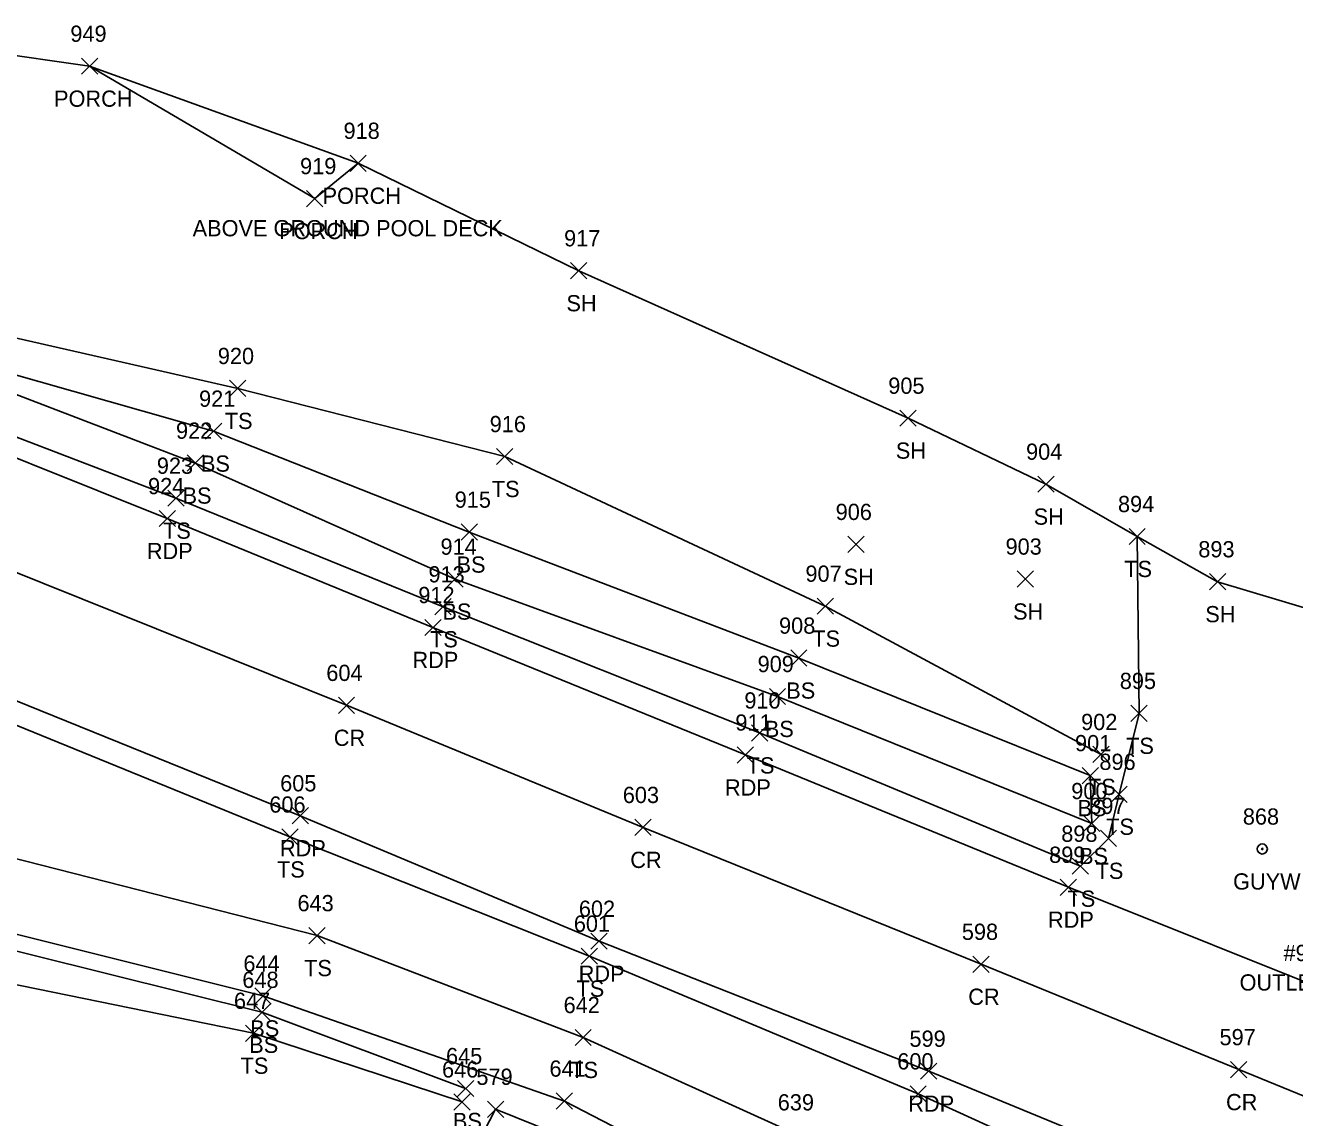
# Model space of a CAD drawing. Extents: x 1599569 to 1610055, y 642560 to 647860.
# Drawn here: x 1602887.6 to 1603043.9, y 647361.4 to 647495.9 of the extents above; entities that cross this region are included whole.
import ezdxf

# ---------------------------------------------------------------- set-up
doc = ezdxf.new("R2010")
doc.units = 0
for name, color, linetype in [('D_C', 7, 'Continuous'), ('L_A', 7, 'Continuous'), ('L_C', 7, 'Continuous'), ('L_I', 7, 'Continuous'), ('L_TIC', 7, 'Continuous'), ('LBF', 7, 'Continuous'), ('LELB', 7, 'Continuous'), ('LSOGP', 7, 'Continuous'), ('P_A', 7, 'Continuous'), ('P_I', 7, 'Continuous'), ('P_TIC', 7, 'Continuous'), ('PET', 7, 'Continuous'), ('PRC', 7, 'Continuous'), ('R_I', 7, 'Continuous'), ('R_TIC', 7, 'Continuous'), ('RDP', 7, 'Continuous'), ('U_A', 7, 'Continuous'), ('U_C', 7, 'Continuous'), ('U_I', 7, 'Continuous'), ('UPGW', 7, 'Continuous')]:
    doc.layers.add(name, color=color, linetype=linetype)

msp = doc.modelspace()

# ---------------------------------------------------------------- linework, layer by layer
at = {"layer": 'L_TIC'}
for points in [[(1602894.48, 647489.89), (1602896.48, 647491.89)], [(1602896.48, 647489.89), (1602894.48, 647491.89)], [(1602927.55, 647477.93), (1602929.55, 647479.93)], [(1602929.55, 647477.93), (1602927.55, 647479.93)], [(1602922.2, 647473.58), (1602924.2, 647475.58)], [(1602924.2, 647473.58), (1602922.2, 647475.58)], [(1602954.71, 647464.69), (1602956.71, 647466.69)], [(1602956.71, 647464.69), (1602954.71, 647466.69)], [(1602912.72, 647450.19), (1602914.72, 647452.19)], [(1602914.72, 647450.19), (1602912.72, 647452.19)], [(1602995.27, 647446.53), (1602997.27, 647448.53)], [(1602997.27, 647446.53), (1602995.27, 647448.53)], [(1602909.75, 647444.93), (1602911.75, 647446.93)], [(1602911.75, 647444.93), (1602909.75, 647446.93)], [(1602907.49, 647440.99), (1602909.49, 647442.99)], [(1602909.49, 647440.99), (1602907.49, 647442.99)], [(1602945.6, 647441.8), (1602947.6, 647443.8)], [(1602947.6, 647441.8), (1602945.6, 647443.8)], [(1603012.24, 647438.4), (1603014.24, 647440.4)], [(1603014.24, 647438.4), (1603012.24, 647440.4)], [(1602905.12, 647436.67), (1602907.12, 647438.67)], [(1602907.12, 647436.67), (1602905.12, 647438.67)], [(1602941.23, 647432.49), (1602943.23, 647434.49)], [(1602943.23, 647432.49), (1602941.23, 647434.49)], [(1603023.48, 647431.95), (1603025.48, 647433.95)], [(1603025.48, 647431.95), (1603023.48, 647433.95)], [(1602988.85, 647430.98), (1602990.85, 647432.98)], [(1602990.85, 647430.98), (1602988.85, 647432.98)], [(1602939.49, 647426.7), (1602941.49, 647428.7)], [(1602941.49, 647426.7), (1602939.49, 647428.7)], [(1603009.71, 647426.71), (1603011.71, 647428.71)], [(1603011.71, 647426.71), (1603009.71, 647428.71)], [(1603033.38, 647426.38), (1603035.38, 647428.38)], [(1603035.38, 647426.38), (1603033.38, 647428.38)], [(1602938, 647423.29), (1602940, 647425.29)], [(1602940, 647423.29), (1602938, 647425.29)], [(1602985.07, 647423.37), (1602987.07, 647425.37)], [(1602987.07, 647423.37), (1602985.07, 647425.37)], [(1602981.82, 647416.97), (1602983.82, 647418.97)], [(1602983.82, 647416.97), (1602981.82, 647418.97)], [(1602979.19, 647412.24), (1602981.19, 647414.24)], [(1602981.19, 647412.24), (1602979.19, 647414.24)], [(1603023.71, 647410.16), (1603025.71, 647412.16)], [(1603025.71, 647410.16), (1603023.71, 647412.16)], [(1602976.99, 647407.75), (1602978.99, 647409.75)], [(1602978.99, 647407.75), (1602976.99, 647409.75)], [(1603019.03, 647405.1), (1603021.03, 647407.1)], [(1603021.03, 647405.1), (1603019.03, 647407.1)], [(1603017.7, 647402.49), (1603019.7, 647404.49)], [(1603019.7, 647402.49), (1603017.7, 647404.49)], [(1603021.25, 647400.19), (1603023.25, 647402.19)], [(1603023.25, 647400.19), (1603021.25, 647402.19)], [(1603017.88, 647396.59), (1603019.88, 647398.59)], [(1603019.88, 647396.59), (1603017.88, 647398.59)], [(1603017.88, 647396.59), (1603019.88, 647398.59)], [(1603019.88, 647396.59), (1603017.88, 647398.59)], [(1602919.15, 647394.93), (1602921.15, 647396.93)], [(1602921.15, 647394.93), (1602919.15, 647396.93)], [(1603019.95, 647394.76), (1603021.95, 647396.76)], [(1603021.95, 647394.76), (1603019.95, 647396.76)], [(1603016.49, 647391.33), (1603018.49, 647393.33)], [(1603018.49, 647391.33), (1603016.49, 647393.33)], [(1602922.49, 647382.78), (1602924.49, 647384.78)], [(1602924.49, 647382.78), (1602922.49, 647384.78)], [(1602956.03, 647380.25), (1602958.03, 647382.25)], [(1602958.03, 647380.25), (1602956.03, 647382.25)], [(1602915.83, 647375.34), (1602917.83, 647377.34)], [(1602917.83, 647375.34), (1602915.83, 647377.34)], [(1602915.7, 647373.33), (1602917.7, 647375.33)], [(1602917.7, 647373.33), (1602915.7, 647375.33)], [(1602914.67, 647370.75), (1602916.67, 647372.75)], [(1602916.67, 647370.75), (1602914.67, 647372.75)], [(1602955.26, 647370.23), (1602957.26, 647372.23)], [(1602957.26, 647370.23), (1602955.26, 647372.23)], [(1602940.78, 647363.94), (1602942.78, 647365.94)], [(1602942.78, 647363.94), (1602940.78, 647365.94)], [(1602996.51, 647363.29), (1602998.51, 647365.29)], [(1602998.51, 647363.29), (1602996.51, 647365.29)], [(1602940.34, 647362.29), (1602942.34, 647364.29)], [(1602942.34, 647362.29), (1602940.34, 647364.29)], [(1602952.95, 647362.4), (1602954.95, 647364.4)], [(1602954.95, 647362.4), (1602952.95, 647364.4)]]:
    msp.add_lwpolyline(points, dxfattribs=at)
at = {"layer": 'LBF'}
msp.add_lwpolyline([(1602928.55, 647478.93), (1602923.2, 647474.58), (1602895.48, 647490.89)], dxfattribs=at)
at = {"layer": 'LELB'}
for points in [[(1603012.49, 647326.24), (1602990.45, 647341.3), (1602973.77, 647353.11), (1602953.95, 647363.4), (1602916.83, 647376.34), (1602879.52, 647385.68), (1602861.45, 647391.05), (1602857.96, 647395.91), (1602856.57, 647396.23), (1602848.89, 647379.86), (1602843.21, 647377.7), (1602818.67, 647385.57), (1602771.25, 647404.63), (1602731.78, 647425.59), (1602689.48, 647442.33), (1602646.26, 647452.13), (1602605.47, 647460.82), (1602615.77, 647472.63), (1602617.29, 647479.52), (1602614.47, 647480.43), (1602602, 647462.58), (1602569.34, 647464.61)], [(1603024.48, 647432.95), (1603024.71, 647411.16), (1603022.25, 647401.19), (1603020.95, 647395.76), (1603017.49, 647392.33), (1602977.99, 647408.75), (1602939, 647424.29), (1602906.12, 647437.67), (1602872.1, 647450.68), (1602855.51, 647461.16), (1602856.65, 647464.1)], [(1603020.03, 647406.1), (1602986.07, 647424.37), (1602946.6, 647442.8), (1602913.72, 647451.19), (1602881.59, 647458.47), (1602856.65, 647464.1)], [(1602941.78, 647364.94), (1602916.7, 647374.33), (1602878.74, 647383.8), (1602864.18, 647385.07), (1602847.83, 647371.45), (1602840.84, 647371.94), (1602817.04, 647381.69), (1602769.81, 647402.39), (1602730.45, 647422.72), (1602686.99, 647437.34), (1602646.16, 647448.05), (1602607.13, 647455.67), (1602560.59, 647462.73), (1602528.15, 647452.11), (1602504.4, 647431.52), (1602495.06, 647409.31), (1602489.51, 647381.97), (1602486.55, 647364.53)], [(1602997.22, 647343.55), (1602982.64, 647359.24), (1602956.26, 647371.23), (1602923.49, 647383.78), (1602881.48, 647394.49), (1602864.86, 647399.2), (1602857.7, 647404.45), (1602852.15, 647401.21), (1602844.53, 647381.78), (1602821.22, 647392.08), (1602783.51, 647427.85), (1602741.14, 647445.48), (1602700.04, 647463.04)], [(1602941.34, 647363.29), (1602915.67, 647371.75), (1602877.66, 647379.52), (1602865.48, 647379.11), (1602848.78, 647367.3), (1602839.38, 647367.46), (1602815.63, 647378.56), (1602768.2, 647398.54), (1602730, 647421.7), (1602686.76, 647436.3), (1602645.94, 647446.93), (1602606.96, 647454.27), (1602560.51, 647460.83), (1602529.36, 647450.31), (1602505.68, 647431.34)], [(1603018.88, 647397.59), (1603018.7, 647403.49), (1602982.82, 647417.97), (1602942.23, 647433.49), (1602910.75, 647445.93), (1602880.53, 647454.49), (1602875.44, 647455.76), (1602873.27, 647454.86)], [(1603018.88, 647397.59), (1602980.19, 647413.24), (1602940.49, 647427.7), (1602908.49, 647441.99), (1602880.19, 647452.83), (1602875.32, 647454.34), (1602874.25, 647451.62), (1602872.66, 647453.06), (1602873.27, 647454.86)], [(1603023.39, 647319.27), (1603033.85, 647321.66), (1603038.01, 647332.85), (1603035.03, 647347.15), (1602997.51, 647364.29), (1602957.03, 647381.25), (1602920.15, 647395.93), (1602878.36, 647413)]]:
    msp.add_lwpolyline(points, dxfattribs=at)
at = {"layer": 'LSOGP'}
msp.add_lwpolyline([(1603050.71, 647422.48), (1603034.38, 647427.38), (1603024.48, 647432.95), (1603013.24, 647439.39), (1602996.27, 647447.53), (1602955.71, 647465.69), (1602928.54, 647478.93), (1602895.48, 647490.88), (1602882.84, 647492.7)], dxfattribs=at)
at = {"layer": 'P_TIC'}
for points in [[(1602904.04, 647434.16), (1602906.04, 647436.16)], [(1602906.04, 647434.16), (1602904.04, 647436.16)], [(1602936.76, 647420.74), (1602938.76, 647422.74)], [(1602938.76, 647420.74), (1602936.76, 647422.74)], [(1602926.12, 647411.15), (1602928.12, 647413.15)], [(1602928.12, 647411.15), (1602926.12, 647413.15)], [(1602975.23, 647405.03), (1602977.23, 647407.03)], [(1602977.23, 647405.03), (1602975.23, 647407.03)], [(1602920.43, 647397.55), (1602922.43, 647399.55)], [(1602922.43, 647397.55), (1602920.43, 647399.55)], [(1602962.63, 647396.11), (1602964.63, 647398.11)], [(1602964.63, 647396.11), (1602962.63, 647398.11)], [(1603015.01, 647388.74), (1603017.01, 647390.74)], [(1603017.01, 647388.74), (1603015.01, 647390.74)], [(1602957.22, 647382.09), (1602959.22, 647384.09)], [(1602959.22, 647382.09), (1602957.22, 647384.09)], [(1603004.25, 647379.25), (1603006.25, 647381.25)], [(1603006.25, 647379.25), (1603004.25, 647381.25)], [(1602997.81, 647366.08), (1602999.81, 647368.08)], [(1602999.81, 647366.08), (1602997.81, 647368.08)], [(1603035.99, 647366.27), (1603037.99, 647368.27)], [(1603037.99, 647366.27), (1603035.99, 647368.27)]]:
    msp.add_lwpolyline(points, dxfattribs=at)
at = {"layer": 'PET'}
for points in [[(1603232.97, 647301.58), (1603195.46, 647316.85), (1603162.96, 647330.21), (1603136.43, 647341.31), (1603134.62, 647343.84), (1603117.95, 647350.67), (1603111.39, 647351.11), (1603082.79, 647362.82), (1603051.7, 647375.44), (1603016.01, 647389.74), (1602976.23, 647406.03), (1602937.76, 647421.74), (1602905.04, 647435.16), (1602871.23, 647448.73)], [(1603222.52, 647275.76), (1603183.61, 647291.56), (1603146.92, 647306.71), (1603109.5, 647322.06), (1603103.75, 647321.89), (1603092.3, 647325.95), (1603063.3, 647338.13), (1603037.55, 647348.42), (1603034.26, 647352.47), (1602998.81, 647367.08), (1602958.22, 647383.09), (1602921.43, 647398.55), (1602879.84, 647415.39)]]:
    msp.add_lwpolyline(points, dxfattribs=at)
at = {"layer": 'PRC'}
msp.add_lwpolyline([(1603227.9, 647288.89), (1603189.52, 647304.82), (1603153.33, 647319.71), (1603109.3, 647337.75), (1603071.31, 647353.23), (1603036.99, 647367.27), (1603005.25, 647380.25), (1602963.63, 647397.11), (1602927.12, 647412.15), (1602885.11, 647429.06)], dxfattribs=at)
at = {"layer": 'R_TIC'}
for points in [[(1602944.48, 647361.39), (1602946.48, 647363.39)], [(1602946.48, 647361.39), (1602944.48, 647363.39)]]:
    msp.add_lwpolyline(points, dxfattribs=at)
at = {"layer": 'RDP'}
msp.add_lwpolyline([(1603020.31, 647281.78), (1603019.38, 647289.31), (1603015.8, 647294.36), (1603007.8, 647299.05), (1603000.04, 647301.12), (1602989.39, 647295.87), (1602983.95, 647288.89), (1602957.29, 647299.5), (1602924.62, 647311.93), (1602935.21, 647342.42), (1602945.48, 647362.39), (1602967.54, 647353.47), (1602980.2, 647342.95), (1602993.04, 647331.17), (1603009.63, 647319.77), (1603021.02, 647313.37), (1603026.7, 647311.82), (1603031.51, 647312.93), (1603035.57, 647315.34), (1603041.42, 647327.93), (1603040.83, 647337.83), (1603037.55, 647348.42)], dxfattribs=at)
at = {"layer": 'UPGW'}
for radius in [0.625, 0.0833]:
    msp.add_circle((1603039.89, 647394.45), radius, dxfattribs=at)

# ---------------------------------------------------------------- texts
at = {"layer": 'D_C'}
msp.add_text('OUTLET BURIED', height=2, dxfattribs=at).set_placement((1603037.09, 647377.01))
at = {"layer": 'L_A'}
for s, p in [('PORCH', (1602891.1, 647485.89)), ('PORCH', (1602924.17, 647473.93)), ('PORCH', (1602918.83, 647469.58)), ('SH', (1602954.2, 647460.69)), ('TS', (1602912.13, 647446.19)), ('SH', (1602994.76, 647442.53)), ('BS', (1602909.19, 647440.93)), ('BS', (1602906.93, 647436.99)), ('TS', (1602945.01, 647437.8)), ('SH', (1603011.73, 647434.4)), ('TS', (1602904.53, 647432.67)), ('BS', (1602940.67, 647428.49)), ('SH', (1602988.34, 647426.98)), ('TS', (1603022.89, 647427.95)), ('BS', (1602938.93, 647422.7)), ('SH', (1603009.2, 647422.71)), ('SH', (1603032.87, 647422.38)), ('TS', (1602937.41, 647419.29)), ('TS', (1602984.48, 647419.37)), ('BS', (1602981.27, 647412.97)), ('BS', (1602978.63, 647408.24)), ('TS', (1603023.12, 647406.16)), ('TS', (1602976.4, 647403.75)), ('TS', (1603018.43, 647401.1)), ('BS', (1603017.14, 647398.49)), ('TS', (1603020.66, 647396.19)), ('BS', (1603017.32, 647392.59)), ('BS', (1603017.32, 647392.59)), ('TS', (1602918.56, 647390.93)), ('TS', (1603019.36, 647390.76)), ('TS', (1603015.9, 647387.33)), ('TS', (1602921.9, 647378.78)), ('TS', (1602955.44, 647376.25)), ('BS', (1602915.27, 647371.34)), ('BS', (1602915.14, 647369.33)), ('TS', (1602914.08, 647366.75)), ('TS', (1602954.67, 647366.23)), ('BS', (1602940.22, 647359.94))]:
    msp.add_text(s, height=2, dxfattribs=at).set_placement(p)
at = {"layer": 'L_C'}
msp.add_text('ABOVE GROUND POOL DECK', height=2, dxfattribs=at).set_placement((1602908.17, 647469.93))
at = {"layer": 'L_I'}
for s, p in [('949', (1602893.11, 647493.89)), ('918', (1602926.75, 647481.93)), ('919', (1602921.4, 647477.58)), ('917', (1602953.91, 647468.69)), ('920', (1602911.27, 647454.19)), ('905', (1602993.83, 647450.53)), ('921', (1602908.96, 647448.93)), ('916', (1602944.75, 647445.8)), ('922', (1602906.12, 647444.99)), ('904', (1603010.8, 647442.4)), ('923', (1602903.76, 647440.67)), ('915', (1602940.44, 647436.49)), ('906', (1602987.35, 647434.98)), ('894', (1603022.12, 647435.95)), ('914', (1602938.69, 647430.7)), ('903', (1603008.27, 647430.71)), ('893', (1603032.01, 647430.38)), ('913', (1602937.21, 647427.29)), ('907', (1602983.63, 647427.37)), ('908', (1602980.38, 647420.97)), ('909', (1602977.74, 647416.24)), ('895', (1603022.34, 647414.16)), ('910', (1602976.11, 647411.75)), ('902', (1603017.58, 647409.1)), ('901', (1603016.83, 647406.49)), ('896', (1603019.83, 647404.19)), ('900', (1603016.36, 647400.59)), ('900', (1603016.36, 647400.59)), ('606', (1602917.61, 647398.93)), ('897', (1603018.58, 647398.76)), ('898', (1603015.13, 647395.33)), ('643', (1602921.08, 647386.78)), ('601', (1602955.11, 647384.25)), ('644', (1602914.42, 647379.34)), ('648', (1602914.29, 647377.33)), ('647', (1602913.26, 647374.75)), ('642', (1602953.85, 647374.23)), ('645', (1602939.37, 647367.94)), ('646', (1602938.88, 647366.29)), ('641', (1602952.11, 647366.4)), ('600', (1602994.94, 647367.29)), ('639', (1602980.22, 647362.24))]:
    msp.add_text(s, height=2, dxfattribs=at).set_placement(p)
at = {"layer": 'P_A'}
for s, p in [('RDP', (1602902.53, 647430.16)), ('RDP', (1602935.24, 647416.74)), ('CR', (1602925.55, 647407.15)), ('RDP', (1602973.72, 647401.03)), ('RDP', (1602918.92, 647393.55)), ('CR', (1602962.06, 647392.11)), ('RDP', (1603013.5, 647384.74)), ('RDP', (1602955.71, 647378.09)), ('CR', (1603003.68, 647375.25)), ('RDP', (1602996.3, 647362.08)), ('CR', (1603035.42, 647362.27))]:
    msp.add_text(s, height=2, dxfattribs=at).set_placement(p)
at = {"layer": 'P_I'}
for s, p in [('924', (1602902.68, 647438.16)), ('912', (1602935.96, 647424.74)), ('604', (1602924.63, 647415.15)), ('911', (1602975, 647409.03)), ('605', (1602918.95, 647401.55)), ('603', (1602961.14, 647400.11)), ('899', (1603013.64, 647392.74)), ('602', (1602955.73, 647386.09)), ('598', (1603002.89, 647383.25)), ('599', (1602996.44, 647370.08)), ('597', (1603034.62, 647370.27))]:
    msp.add_text(s, height=2, dxfattribs=at).set_placement(p)
at = {"layer": 'R_I'}
msp.add_text('579', height=2, dxfattribs=at).set_placement((1602943.11, 647365.39))
at = {"layer": 'U_A'}
msp.add_text('GUYW', height=2, dxfattribs=at).set_placement((1603036.29, 647389.45))
at = {"layer": 'U_C'}
msp.add_text('#9/1-8/6', height=2, dxfattribs=at).set_placement((1603042.5, 647380.64))
at = {"layer": 'U_I'}
msp.add_text('868', height=2, dxfattribs=at).set_placement((1603037.49, 647397.45))

doc.saveas('drawing.dxf')
